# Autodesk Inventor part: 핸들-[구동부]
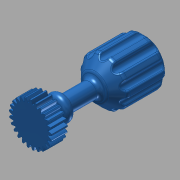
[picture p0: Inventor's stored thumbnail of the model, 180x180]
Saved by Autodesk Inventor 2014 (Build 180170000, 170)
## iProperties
Created: 2017-04
Part Number: 핸들-[구동부]
Material: 강철, 연강
Document SubType Name: Modeling
Designer: mduedu
Categories: <?xml version="1.0" encoding="UTF-16"?> <MemberInstance><Categories><FamilyTemplate><FamilyTemplateParameter ValueType="xs:double" Id="1" ObjectReferenceKey="da
Density: 1 g/cm^3
Appearance: 청록색
CustomPartVersion: 1
Author: mduedu
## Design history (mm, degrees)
sketch "Sketch1"
  geometry: C1 r 13.5 at (0, 0)
  constraints: 1 centre point
  dimensions: "d0" = 27 diameter of C1 (= da_da)
extrude "Extrusion1" new body sketch "Sketch1" distance "d1" = 10 (= da_b); taper "d2" = 0 deg
workplane "Work Plane2"
sketch "Sketch2"
  geometry: C1 r 13.5 at (0, 0) reference; C2 r 12.5 at (0, 0)
  constraints: 1 centre point, 1 coincident
  dimensions: "d3" = 25 diameter of C2 (= da_dw)
feature "피치 지름" sketch "Sketch2" dims "d4" = 10, "d5" = 0
workplane "Work Plane8"
workplane "Work Plane9"
feature "스퍼 기어" dims "da_b" = 10, "da_d" = 25, "da_aw" = 25, "da_da" = 27, "da_df" = 22.5, "da_dw" = 25, angle "da_beta" = 0 deg, "da_lefttooth" = 0, "da_righttooth" = 0
sketch "스케치3"
  geometry: C1 r 5 at (0, 0); 1 further point
  constraints: 1 centre point, 1 coincident
  dimensions: "d49" = 10 diameter of C1
extrude "돌출2" join sketch "스케치3" distance "d50" = 60; taper "d51" = 0 deg
sketch "스케치4"
  geometry: C1 r 15 at (0, 0); 1 further point
  constraints: 1 centre point, 1 coincident
  dimensions: "d52" = 30 diameter of C1
extrude "돌출3" join sketch "스케치4" distance "d53" = 30; taper "d54" = 0 deg
chamfer "모따기1" distance "d55" = 7; stored, may be unused: second distance "d56" = 2, angle "d57" = 45 deg
sketch "스케치5"
  geometry: L1 (0, 2.2)-(0, -13.2) reference; L2 (0, -5)-(8, -5); L3 (8, -5)-(8, -11); L4 (8, -11)-(0, -11); L5 (0, -11)-(0, -5); 1 further point
  constraints: 8 end point, 2 parallel, 1 horizontal, 1 perpendicular, 1 point on line
  dimensions: "d58" = 5 distance from line of L2 point (0, 0); "d59" = 6 distance of L2.end L3.end; "d60" = 16 diameter of L3 L1
revolve "회전1" sketch "스케치5" stored, may be unused: angle "d61" = 90 deg
fillet "모깎기1" dims "d62" = 3
fillet "모깎기2" dims "d65" = 3
sketch "스케치9"
  geometry: L1 (15, -60)-(-15, -60) reference; L2 (0, -60)-(0, 0); L3 (0, -66.771)-(0, -60); A1 r 20 centre (0, -46.771) between (0, -66.771) and (15, -60)
  constraints: 4 end point, 2 point on circle, 1 centre point, 1 collinear, 1 line through centre, 1 midpoint, 1 perpendicular
  dimensions: "d84" = 20 radius of A1
revolve "회전4" sketch "스케치9" stored, may be unused: angle "d86" = 90 deg
fillet "모깎기3" dims "d72" = 3
sketch "스케치6"
  geometry: C1 r 2.5 at (0, 15); 2 further points
  constraints: 2 vertical alignment, 1 centre point, 1 other
  dimensions: "d66" = 5 diameter of C1
extrude "돌출4" cut sketch "스케치6" stored distance "d67" = 60; taper "d68" = 0 deg
fillet "모깎기4" dims "d73" = 1
node "작업 평면12"
sketch "스케치10"
  geometry: C1 r 6 at (0, 0); 1 further point
  constraints: 1 centre point, 1 coincident
  dimensions: "d87" = 12 diameter of C1
extrude "돌출5" cut sketch "스케치10" distance "d88" = 5; taper "d89" = 0 deg
fillet "모깎기5" dims "d90" = 1
body "Solid1"
pattern_circular "원형 패턴2" dims angle "d75" = 360 deg
body "Srf1"
other parameters: "d16" = 25 (= da_aw), "d17" = 0, "d34" = 1.25664 (computed from da_z), "d39" = 0, "d41" = 0, "d43" = 25 (= da_aw), "d46" = 25 (= da_aw), "d47" = 0, "d48" = 0
